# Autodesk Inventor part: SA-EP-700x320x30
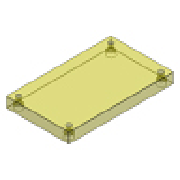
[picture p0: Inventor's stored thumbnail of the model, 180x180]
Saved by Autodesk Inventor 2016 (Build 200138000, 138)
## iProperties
Created: 2015-02
Part Number: SA-EP-700x320x30
Material: S 55 C
Description: Ejector Plate
Document SubType Name: Modeling
Designer: Sandeep
Standard Revision: 1
Manufacturer: FUTABA
Language: en-US
Size Designation: 700x320x30
Categories: <MemberInstance><Categories><Category DisplayName="Mold" InternalName="349578f2-f4d4-4954-8c09-8e99297a61c0" Mnemonic="MOLD"><Category DisplayName="Mold Plates"
Density: 7.85 g/cm^3
Appearance: Clear - Yellow
IsCustomPart: 1
Author: Sandeep
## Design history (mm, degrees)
sketch "Sketch1"
  geometry: L1 (-160, 350)-(160, 350); L2 (160, 350)-(160, -350); L3 (160, -350)-(-160, -350); L4 (-160, -350)-(-160, 350); 4 further points
  constraints: 8 end point, 2 midpoint, 2 parallel, 1 horizontal, 1 horizontal alignment, 1 perpendicular, 1 vertical alignment
  dimensions: "d74" = 147 horizontal distance of point (0, 0) point (-147, 337) (= 0.5 x S2_W); "d75" = 337 vertical distance of point (0, 0) point (-147, 337) (= 0.5 x S2_L); "d92" = 320 distance between parallel lines of L2 L4 (= W_); "d93" = 700 distance between parallel lines of L3 L1 (= L)
extrude "Extrusion1" new body sketch "Sketch1" distance "d20" = 30 (= H_); taper "d30" = 0 deg
body "Solid1"
hole "Hole1" sketch "Sketch1" diameter "d76" = 14 (= S2_d1); stored, may be unused: countersink angle "d80" = 90 deg, drill point angle "d82" = 0 deg; dims "d77" = 6, "d78" = 20 (= S2_d2), "d79" = 13 (= S2_k), "d81" = 30 (= H_)
pattern_linear "Rectangular Pattern1" dims "d85" = 674 (computed from S2_L, Nl), "d88" = 294 (computed from S2_W, Nw)
chamfer "Chamfer1" distance "d89" = 0.5; stored, may be unused: second distance "d90" = 2, angle "d91" = 45 deg
other parameters: "L" = 700 [user parameter; used in 1 equation term], "W_" = 320 [user parameter; used in 1 equation term], "H_" = 30 [user parameter; used in 2 equation terms], "S2_W" = 294 [user parameter; used in 2 equation terms], "S2_d1" = 14 [user parameter; used in 1 equation term], "S2_d2" = 20 [user parameter; used in 1 equation term], "S2_k" = 13 [user parameter; used in 1 equation term], "S2_L" = 674 [user parameter; used in 2 equation terms]
